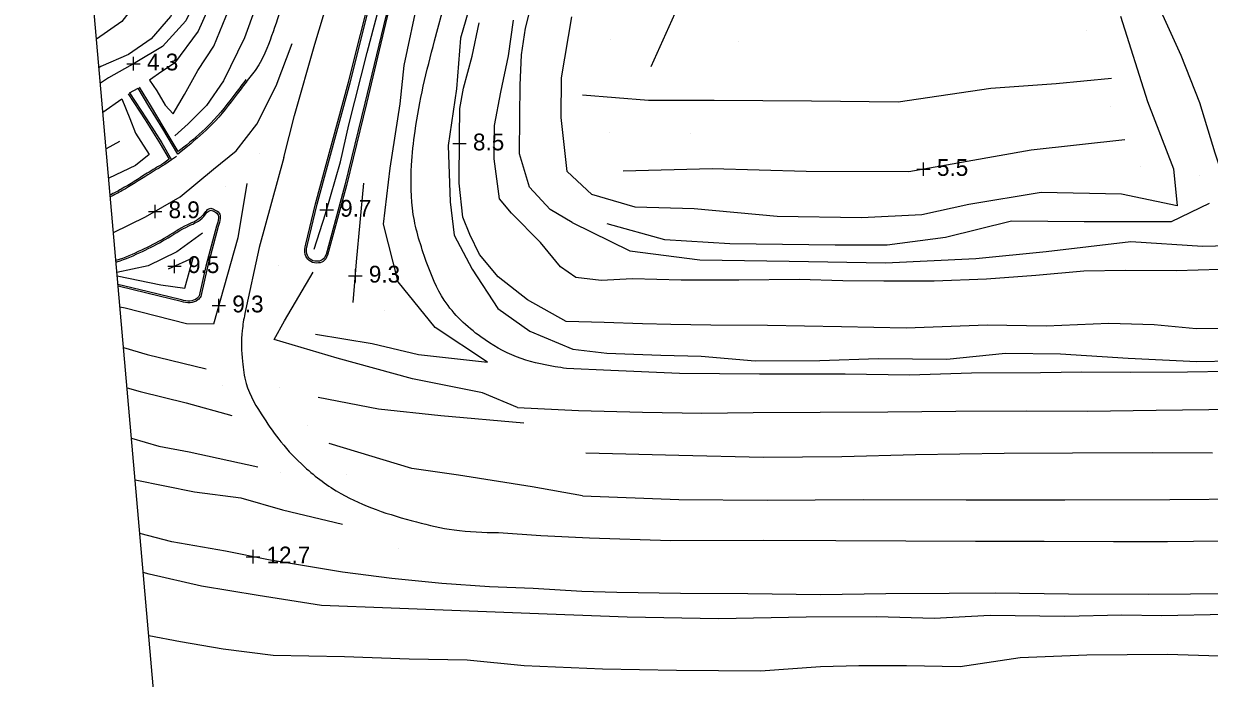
# Model space of a CAD drawing. Extents: x 2316231 to 2323598, y 363169 to 371906.
# Drawn here: x 2319735.1 to 2320087.6, y 371334.8 to 371529.6 of the extents above; entities that cross this region are included whole.
import ezdxf

# ---------------------------------------------------------------- set-up
doc = ezdxf.new("R2010")
doc.units = 0
for name, color, linetype in [('RD_DTM_BkLn1', 7, 'Continuous'), ('RD_DTM_Spot', 7, 'Continuous'), ('RD_DTM_TinHull', 7, 'Continuous'), ('RD_DTM_Void', 7, 'Continuous'), ('RD_EX_BldgApp', 7, 'Continuous'), ('RD_EX_H2O', 7, 'Continuous'), ('RD_EX_Road', 7, 'Continuous')]:
    doc.layers.add(name, color=color, linetype=linetype)

msp = doc.modelspace()

# ---------------------------------------------------------------- linework, layer by layer
at = {"layer": 'RD_DTM_BkLn1'}
msp.add_line((2319763.526, 371494.513), (2319759.555, 371492.33), dxfattribs=at)
for points in [[(2320049.846, 371673.711), (2320031.166, 371680.322), (2320011.496, 371694.526), (2319994.37, 371705.014), (2319981.234, 371711.519), (2319968.184, 371686.204), (2319958.508, 371652.066), (2319949.301, 371614.668), (2319942.663, 371571.919), (2319935.765, 371548.525), (2319921.552, 371516.751)], [(2319812.381, 371489.729), (2319815.599, 371502.253), (2319821.626, 371523.449), (2319828.632, 371546.868), (2319834.036, 371568.258)], [(2319781.735, 371564.435), (2319774.708, 371543.795), (2319764.274, 371530.252), (2319756.706, 371524.967)], [(2319790.561, 371562.712), (2319786.887, 371551.699), (2319783.244, 371540.316), (2319778.71, 371531.723), (2319772.916, 371525.058), (2319766.174, 371520.396), (2319757.964, 371516.807), (2319757.438, 371516.58)], [(2319798.774, 371559.329), (2319793.255, 371541.612), (2319786.877, 371527.38), (2319779.91, 371517.8), (2319776.115, 371515.347), (2319772.422, 371512.765), (2319774.628, 371509.599), (2319777.157, 371505.363), (2319779.52, 371502.727), (2319782.837, 371508.498), (2319786.819, 371515.661), (2319791.613, 371522.849), (2319795.13, 371531.571), (2319798.014, 371537.984), (2319801.204, 371545.598), (2319805.444, 371558.387)], [(2319812.74, 371559.289), (2319807.211, 371543.495), (2319800.714, 371525.408), (2319794.47, 371512.587), (2319789.36, 371505.195), (2319783.975, 371499.74), (2319779.958, 371496.236)], [(2319821.425, 371462.526), (2319824.814, 371473.033), (2319829.285, 371488.493), (2319831.695, 371499.453), (2319837.148, 371520.981), (2319841.563, 371537.542), (2319845.949, 371556.235)], [(2319847.027, 371505.718), (2319848.181, 371517.122), (2319852.434, 371537.287), (2319858.485, 371558.483)], [(2319872.114, 371550.295), (2319864.903, 371525.269), (2319863.761, 371510.194), (2319861.24, 371493.318), (2319861.848, 371476.6), (2319862.994, 371466.614), (2319868.423, 371456.539), (2319876.068, 371444.872), (2319885.5, 371438.058), (2319898.333, 371432.763), (2319908.403, 371431.534), (2319924.447, 371430.992), (2319936.487, 371430.688), (2319952.486, 371429.313), (2319971.745, 371429.402), (2319989.077, 371429.956), (2320009.48, 371429.764), (2320026.931, 371431.555), (2320043.338, 371431.345), (2320063.392, 371430.104), (2320083.888, 371429.1), (2320105.028, 371429.489)], [(2319898.097, 371470.415), (2319891.546, 371474.285), (2319885.435, 371480.941), (2319882.47, 371490.869), (2319882.612, 371501.95), (2319882.709, 371511.318), (2319883.033, 371520.335), (2319884.2, 371528.241), (2319886.995, 371539.38), (2319891.052, 371547.852)], [(2320061.139, 371531.764), (2320069.152, 371506.381), (2320076.897, 371486.352), (2320078.043, 371475.428), (2320061.503, 371478.859), (2320037.527, 371479.375), (2320016.103, 371475.828), (2320002.132, 371472.741), (2319984.148, 371471.837), (2319959.046, 371472.228), (2319934.42, 371474.5), (2319916.893, 371475.026), (2319903.971, 371478.735), (2319896.682, 371485.615), (2319894.884, 371501.654), (2319894.989, 371513.465), (2319898.001, 371531.631)], [(2320101.055, 371468.289), (2320093.676, 371478.111), (2320089.291, 371491.08), (2320084.711, 371505.985), (2320079.206, 371520.103), (2320072.763, 371534.256)], [(2320099.544, 371438.986), (2320083.642, 371438.773), (2320071.139, 371440.01), (2320057.663, 371440.333), (2320039.021, 371439.623), (2320021.537, 371439.893), (2319997.415, 371438.986), (2319978.208, 371439.418), (2319956.186, 371439.746), (2319939.396, 371439.88), (2319927.458, 371440.033), (2319919.02, 371440.315), (2319907.629, 371440.669), (2319896.33, 371440.988), (2319884.89, 371447.423), (2319876.083, 371454.229), (2319870.552, 371460.866), (2319867.745, 371466.878), (2319865.611, 371472.024), (2319864.559, 371482.135), (2319864.643, 371495.881), (2319864.682, 371504.369), (2319865.859, 371510.387), (2319868.366, 371519.874), (2319870.497, 371529.806)], [(2320090.735, 371456.435), (2320077.853, 371456.079), (2320062.625, 371456.135), (2320050.254, 371455.9), (2320035.983, 371454.682), (2320021.284, 371453.538), (2320005.782, 371452.984), (2319990.796, 371452.933), (2319978.65, 371453.1), (2319965.604, 371453.499), (2319947.64, 371453.301), (2319930.546, 371453.253), (2319916.029, 371453.671), (2319906.712, 371453.142), (2319899.195, 371454.014), (2319894.616, 371457.269), (2319888.71, 371464.501), (2319880.102, 371473.228), (2319876.52, 371477.454), (2319874.912, 371489.391), (2319875.039, 371499.268), (2319876.926, 371509.157), (2319879.161, 371520.014), (2319880.676, 371530.66)], [(2319761.731, 371467.402), (2319771.31, 371472.074), (2319781.532, 371478.057), (2319791.504, 371486.314), (2319798.198, 371491.787), (2319804.379, 371499.675), (2319810.108, 371511.113), (2319814.866, 371523.698)], [(2320058.529, 371513.315), (2320042.016, 371511.639), (2320022.648, 371510.266), (2319995.057, 371506.242), (2319969.248, 371506.549), (2319940.345, 371506.688), (2319920.786, 371506.742), (2319901.176, 371508.267)], [(2319758.603, 371503.233), (2319764.199, 371507.231), (2319766.613, 371501.352), (2319768.329, 371496.987), (2319769.896, 371494.535), (2319772.348, 371490.659), (2319768.334, 371487.421), (2319760.318, 371483.591)], [(2319821.854, 371437.24), (2319838.655, 371434.373), (2319852.453, 371431.162), (2319872.944, 371428.861), (2319857.349, 371439.136), (2319846.407, 371452.768), (2319842.076, 371469.951), (2319844.048, 371486.544), (2319847.027, 371505.718)], [(2320062.405, 371494.991), (2320034.641, 371491.896), (2319998.266, 371485.541), (2319967.729, 371485.619), (2319939.761, 371486.418), (2319913.255, 371485.692)], [(2319812.381, 371489.729), (2319805.09, 371462.967), (2319800.785, 371443.324)], [(2319833.045, 371446.616), (2319833.999, 371458.74), (2319836.198, 371482.128)], [(2319801.362, 371481.995), (2319798.7, 371465.828), (2319791.526, 371440.13), (2319783.468, 371440.314), (2319765.231, 371444.972), (2319763.667, 371445.226)], [(2320087.489, 371476.06), (2320076.21, 371470.646), (2320050.349, 371470.583), (2320028.72, 371470.86), (2320009.144, 371465.923), (2319991.825, 371463.678), (2319976.318, 371463.634), (2319945.022, 371464.093), (2319925.663, 371465.302), (2319908.492, 371470.073)], [(2319788.214, 371467.213), (2319780.592, 371461.648), (2319772.05, 371457.496), (2319762.767, 371455.543)], [(2319762.856, 371454.518), (2319775.846, 371451.9), (2319782.921, 371450.895), (2319785.456, 371459.883), (2319777.967, 371456.505)], [(2319881.908, 371415.371), (2319871.508, 371419.777), (2319850.623, 371423.901), (2319828.212, 371430.095), (2319809.546, 371435.661), (2319812.547, 371441.193), (2319821.117, 371455.686)], [(2319764.718, 371433.198), (2319771.759, 371431.154), (2319789.307, 371426.876)], [(2319765.766, 371421.187), (2319769.684, 371420.179), (2319783.363, 371416.749), (2319796.911, 371412.963)], [(2319822.644, 371418.458), (2319840.491, 371414.94), (2319859.122, 371413.022), (2319883.726, 371410.785)], [(2319881.908, 371415.371), (2319900.032, 371414.455), (2319918.995, 371413.958), (2319936.652, 371413.685), (2319951.941, 371413.941), (2319971.861, 371414.01), (2319991.966, 371414.134), (2320012.223, 371414.292), (2320033.231, 371414.347), (2320051.331, 371414.3), (2320071.74, 371414.629), (2320095.217, 371414.838)], [(2319767.07, 371406.248), (2319775.184, 371403.849), (2319784.254, 371402.216), (2319804.636, 371397.728)], [(2319901.213, 371389.148), (2319886.238, 371391.772), (2319864.303, 371395.296), (2319850.42, 371397.245), (2319825.872, 371404.682)], [(2319902.198, 371401.851), (2319929.798, 371401.196), (2319954.897, 371400.562), (2319978.293, 371400.807), (2320000.165, 371401.418), (2320026.527, 371401.775), (2320046.887, 371401.908), (2320070.548, 371402.01), (2320088.507, 371401.873)], [(2319768.152, 371393.86), (2319785.873, 371390.279), (2319799.608, 371388.528), (2319812.012, 371384.976), (2319829.848, 371380.624)], [(2319901.213, 371389.148), (2319929.872, 371387.982), (2319956.088, 371387.785), (2319984.684, 371388.044), (2320015.289, 371387.872), (2320044.565, 371387.879), (2320075.8, 371388.046), (2320099.137, 371388.176)], [(2319876.22, 371378.154), (2319888.844, 371377.309), (2319903.276, 371376.592), (2319927.388, 371375.819), (2319954.882, 371375.919), (2319976.559, 371375.78), (2319997.357, 371375.687), (2320018.073, 371375.595), (2320038.479, 371375.624), (2320059.079, 371375.522), (2320075.153, 371375.501), (2320098.411, 371375.805)], [(2320092.686, 371353.829), (2320073.329, 371353.394), (2320061.531, 371353.557), (2320044.572, 371353.16), (2320022.445, 371353.455), (2320005.758, 371352.627), (2319988.718, 371353.111), (2319967.744, 371353.021), (2319941.681, 371352.498), (2319914.484, 371352.951), (2319890.687, 371353.939), (2319844.27, 371355.634), (2319823.633, 371356.5), (2319804.783, 371359.429), (2319787.876, 371362.205), (2319772.346, 371365.774), (2319770.555, 371366.328)], [(2320090.454, 371341.432), (2320075.128, 371341.918), (2320051.119, 371341.704), (2320031.374, 371340.857), (2320013.507, 371338.249), (2319997.506, 371338.535), (2319983.366, 371338.565), (2319971.99, 371338.213), (2319954.105, 371336.948), (2319929.186, 371337.14), (2319907.118, 371337.539), (2319883.83, 371338.497), (2319866.864, 371340.243), (2319849.647, 371340.545), (2319830.409, 371341.185), (2319809.187, 371341.642), (2319794.353, 371343.512), (2319781.665, 371345.678), (2319772.204, 371347.44)]]:
    msp.add_lwpolyline(points, dxfattribs=at)
msp.add_spline([(2319800.785, 371443.324), (2319800.002, 371438.261), (2319800.081, 371429.054), (2319801.191, 371422.554), (2319806.398, 371412.308), (2319811.541, 371405.132), (2319818.545, 371397.723), (2319829.364, 371389.779), (2319839.806, 371385.013), (2319851.803, 371381.339), (2319862.994, 371378.949), (2319876.22, 371378.154)], degree=3, dxfattribs=at)
at = {"layer": 'RD_DTM_Spot'}
for p, q in [((2319909.583, 371524.953), (2319909.583, 371524.953)), ((2320051.153, 371527.515), (2320051.153, 371527.515)), ((2319947.677, 371524.192), (2319947.677, 371524.192)), ((2320058.237, 371505.015), (2320058.237, 371505.015)), ((2319909.244, 371497.104), (2319909.244, 371497.104)), ((2319933.189, 371496.855), (2319933.189, 371496.855)), ((2319805.158, 371490.887), (2319805.158, 371490.887)), ((2320067.143, 371486.975), (2320067.143, 371486.975)), ((2320084.608, 371484.342), (2320084.608, 371484.342)), ((2319795.063, 371481.15), (2319795.063, 371481.15)), ((2319810.883, 371457.705), (2319810.883, 371457.705)), ((2319842.302, 371444.239), (2319842.302, 371444.239)), ((2319794.176, 371421.868), (2319794.176, 371421.868)), ((2319811.078, 371421.409), (2319811.078, 371421.409)), ((2319819.35, 371409.977), (2319819.35, 371409.977)), ((2319811.484, 371396.169), (2319811.484, 371396.169)), ((2319831, 371395.491), (2319831, 371395.491)), ((2319846.57, 371373.3), (2319846.57, 371373.3))]:
    msp.add_line(p, q, dxfattribs=at)
at = {"layer": 'RD_DTM_TinHull'}
msp.add_lwpolyline([(2319782.271, 371232.132), (2319735.05, 371773.026), (2320925.274, 371905.831), (2321343.399, 371858.015), (2321109.741, 371125.092), (2321259.088, 370783.878), (2321451.866, 370308.131), (2321545.882, 369878.312), (2321496.483, 369600.925), (2321592.742, 369376.322), (2321772.553, 369180.585), (2321930.831, 369046.826), (2322410.389, 369187.058), (2322700.489, 369322.074), (2323031.423, 369488.086), (2323384.71, 369626.658), (2323598.112, 369182.404), (2323506.079, 369141.824), (2322749.057, 368805.183), (2322437.788, 368637.943)], dxfattribs=at)
at = {"layer": 'RD_DTM_Void'}
for p, q in [((2319765.709, 371517.678), (2319769.709, 371517.678)), ((2319767.709, 371515.678), (2319767.709, 371519.678)), ((2319862.63, 371493.887), (2319866.63, 371493.887)), ((2319864.63, 371491.887), (2319864.63, 371495.887)), ((2320000.591, 371486.296), (2320004.591, 371486.296)), ((2320002.591, 371484.296), (2320002.591, 371488.296)), ((2319774.115, 371471.715), (2319774.115, 371475.715)), ((2319825.136, 371472.148), (2319825.136, 371476.148)), ((2319772.115, 371473.715), (2319776.115, 371473.715)), ((2319823.136, 371474.148), (2319827.136, 371474.148)), ((2319779.913, 371455.383), (2319779.913, 371459.383)), ((2319777.913, 371457.383), (2319781.913, 371457.383)), ((2319831.669, 371454.548), (2319835.669, 371454.548)), ((2319833.669, 371452.548), (2319833.669, 371456.548)), ((2319793.075, 371443.679), (2319793.075, 371447.679)), ((2319791.075, 371445.679), (2319795.075, 371445.679)), ((2319803.235, 371368.989), (2319803.235, 371372.989)), ((2319801.235, 371370.989), (2319805.235, 371370.989))]:
    msp.add_line(p, q, dxfattribs=at)
at = {"layer": 'RD_EX_BldgApp'}
msp.add_line((2319766.549, 371508.984), (2319769.034, 371510.388), dxfattribs=at)
at = {"layer": 'RD_EX_H2O'}
for points in [[(2319795.254, 371564.806), (2319789.594, 371543.315), (2319783.21, 371530.403), (2319776.36, 371522.755), (2319768.146, 371517.927), (2319760.283, 371513.442), (2319757.848, 371511.886)], [(2319898.097, 371470.415), (2319915.28, 371462.042), (2319936.125, 371459.354), (2319962.604, 371458.888), (2319991.329, 371458.392), (2320018.12, 371459.682), (2320039.05, 371461.822), (2320064.229, 371464.742), (2320085.59, 371463.403), (2320105.029, 371463.895)]]:
    msp.add_lwpolyline(points, dxfattribs=at)
at = {"layer": 'RD_EX_Road'}
for p, q in [((2319780.505, 371490.08), (2319778.987, 371489.115)), ((2319771.797, 371449.857), (2319763.077, 371451.988)), ((2319771.68, 371449.371), (2319763.123, 371451.462)), ((2319781.897, 371446.912), (2319771.68, 371449.371)), ((2319781.994, 371447.403), (2319771.797, 371449.857))]:
    msp.add_line(p, q, dxfattribs=at)
for points in [[(2319818.907, 371463.971), (2319821.817, 371475.989), (2319831.614, 371512.134), (2319838.817, 371541.052), (2319844.242, 371563.101), (2319850.05, 371585.93), (2319856.213, 371609.434), (2319862.729, 371635.013), (2319867.796, 371654.987), (2319873.925, 371678.585), (2319880.388, 371703.382), (2319886.534, 371725.976), (2319890.81, 371744.531)], [(2319819.404, 371463.897), (2319822.302, 371475.865), (2319832.098, 371512.009), (2319839.303, 371540.931), (2319844.727, 371562.98), (2319850.534, 371585.805), (2319856.698, 371609.309), (2319863.213, 371634.89), (2319868.28, 371654.863), (2319874.409, 371678.459), (2319880.872, 371703.253), (2319887.019, 371725.854), (2319891.295, 371744.41)], [(2319850.482, 371562.028), (2319842.671, 371531.829), (2319836.502, 371505.906), (2319830.563, 371481.578), (2319824.937, 371460.885)], [(2319850.966, 371561.903), (2319843.156, 371531.708), (2319836.988, 371505.789), (2319831.048, 371481.453), (2319825.396, 371460.669)], [(2319857.204, 371524.487), (2319860.463, 371536.675), (2319867.536, 371561.714)], [(2319783.762, 371493.084), (2319780.849, 371490.782), (2319776.371, 371498.262), (2319772.289, 371505.066), (2319769.034, 371510.388)], [(2319783.44, 371493.466), (2319780.986, 371491.527), (2319776.8, 371498.519), (2319772.717, 371505.325), (2319769.46, 371510.649)], [(2319766.129, 371508.713), (2319771.124, 371500.985), (2319775.647, 371493.825), (2319778.327, 371489.252), (2319776.711, 371488.075)], [(2319766.549, 371508.984), (2319771.545, 371501.254), (2319776.074, 371494.085), (2319778.987, 371489.115)], [(2319778.987, 371489.115), (2319778.987, 371489.115), (2319776.988, 371487.658)], [(2319792.421, 371469.347), (2319789.245, 371457.389), (2319787.26, 371448.63)], [(2319792.907, 371469.226), (2319789.731, 371457.269), (2319787.718, 371448.39)], [(2319998.382, 371425.019), (2319979.289, 371425.252), (2319953.79, 371425.347), (2319930.063, 371425.478), (2319909.6, 371426.4), (2319896.394, 371427.009)], [(2320093.068, 371426.099), (2320081.056, 371425.905), (2320064.101, 371425.81), (2320049.695, 371425.844), (2320037.418, 371425.7), (2320016.873, 371425.593), (2319998.382, 371425.019)], [(2320094.502, 371359.978), (2320069.496, 371359.72), (2320045.734, 371359.827), (2320023.909, 371360.142), (2320010.266, 371360.062), (2319991.41, 371359.898), (2319971.964, 371359.684), (2319950.358, 371359.961), (2319930.324, 371360.032), (2319911.452, 371360.343), (2319901.022, 371360.662), (2319886.534, 371361.531), (2319873.501, 371362.046), (2319859.339, 371363.015), (2319844.535, 371364.548), (2319829.817, 371366.392), (2319815.557, 371368.775), (2319807.872, 371370.055), (2319795.097, 371372.627), (2319779.071, 371375.461), (2319769.546, 371377.894)]]:
    msp.add_lwpolyline(points, dxfattribs=at)
for points in [[(2319810.923, 371532.249), (2319807.319, 371522.162), (2319804.575, 371516.719), (2319801.535, 371512.717)], [(2319896.394, 371427.009), (2319893.065, 371427.503), (2319881.557, 371430.453), (2319870.979, 371436.379), (2319860.106, 371447.277), (2319854.753, 371458.845), (2319850.879, 371472.838), (2319850.372, 371487.505), (2319851.393, 371497.556), (2319853.858, 371511.004), (2319857.204, 371524.487)], [(2319801.134, 371513.015), (2319798.137, 371508.987), (2319790.723, 371500.007), (2319783.44, 371493.466)], [(2319801.535, 371512.717), (2319798.531, 371508.679), (2319791.085, 371499.66), (2319783.762, 371493.084)], [(2319776.711, 371488.075), (2319771.72, 371485.057), (2319764.063, 371480.333), (2319760.756, 371478.571)], [(2319776.988, 371487.658), (2319771.981, 371484.63), (2319764.312, 371479.899), (2319760.804, 371478.029)], [(2319762.45, 371459.174), (2319762.588, 371459.215), (2319770.143, 371462.28), (2319776.846, 371465.772), (2319783.87, 371469.851), (2319788.294, 371472.609), (2319790.695, 371474.651), (2319791.985, 371474.113), (2319793.382, 371472.856), (2319793.47, 371471.628), (2319792.907, 371469.226)], [(2319762.494, 371458.665), (2319762.754, 371458.743), (2319770.353, 371461.826), (2319777.087, 371465.334), (2319784.128, 371469.423), (2319788.59, 371472.204), (2319790.785, 371474.072), (2319791.714, 371473.685), (2319792.897, 371472.62), (2319792.966, 371471.668), (2319792.421, 371469.347)], [(2319825.396, 371460.669), (2319824.087, 371458.821), (2319822.124, 371458.371), (2319819.945, 371459.094), (2319818.729, 371460.916), (2319818.907, 371463.971)], [(2319824.937, 371460.885), (2319823.79, 371459.266), (2319822.149, 371458.89), (2319820.265, 371459.515), (2319819.238, 371461.054), (2319819.404, 371463.897)], [(2319787.718, 371448.39), (2319786.837, 371447.428), (2319784.509, 371446.508), (2319781.897, 371446.912)], [(2319787.26, 371448.63), (2319786.546, 371447.851), (2319784.451, 371447.023), (2319781.994, 371447.403)]]:
    msp.add_spline(points, degree=3, dxfattribs=at)

# ---------------------------------------------------------------- texts
at = {"layer": 'RD_DTM_Void'}
for s, p in [('4.3', (2319771.709, 371515.678)), ('8.5', (2319868.63, 371491.887)), ('5.5', (2320006.591, 371484.296)), ('8.9', (2319778.115, 371471.715)), ('9.7', (2319829.136, 371472.148)), ('9.5', (2319783.913, 371455.383)), ('9.3', (2319837.669, 371452.548)), ('9.3', (2319797.075, 371443.679)), ('12.7', (2319807.235, 371368.989))]:
    msp.add_text(s, height=5, dxfattribs=at).set_placement(p)

doc.saveas('drawing.dxf')
